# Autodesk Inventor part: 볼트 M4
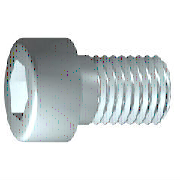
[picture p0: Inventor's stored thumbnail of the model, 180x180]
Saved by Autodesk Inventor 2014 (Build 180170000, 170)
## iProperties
IsCustomPart: 0
Created: 2016-04
Part Number: 볼트 M4
Material: 강철, 연강
Description: 6각머리 태핑 나사
Document SubType Name: Modeling
Standard: KS B 1003
Designer: mdu
Standards Organization: KS
Language: ko-KR
Size Designation: M 4 x 10
Categories: <MemberInstance><Categories><Category DisplayName="조임쇠" InternalName="e4da775c-781d-43d5-af7c-5136215cf5a6" Mnemonic="FSTN"><Category DisplayName="볼트" InternalN
Density: 7.86 g/cm^3
Mass: 2.0371 g
Surface Area: 3.0572 cm^2
Volume: 0.259174 cm^3
Appearance: 금속 1800F 열
Author: mdu
Revision Number: 1
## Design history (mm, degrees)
sketch "스케치1"
  geometry: L1 (-1, 0)-(10, 0); L2 (10, 0)-(10, 2); L3 (10, 2)-(1.75, 2); L4 (1.75, 2)-(1.32, 2); L5 (1.32, 2)-(0, 2); L6 (0, 2)-(0, 3.5); L7 (0, 3.5)-(-4, 3.5); L8 (-4, 3.5)-(-4, 1.732); L9 (-4, 1.732)-(-2, 1.732); L10 (-2, 1.732)-(-1, 0); L11 (-6.8, 0)-(12.8, 0) reference; L12 (0, -0.7)-(0, 4.2) reference; L13 (1.75, 2)-(0, 2)
  constraints: 22 end point, 6 parallel, 2 collinear, 2 perpendicular, 1 horizontal, 1 point on line
  dimensions: "d1" = 8.25 distance from line of L3.end L2 (= GEL); "d2" = 0.42952 distance of L4.end L3.end (computed from GAL); "d3" = 4 distance between parallel lines of L8 L6 (= KOH); "d4" = 2 distance of L8.end L9.end (= INTI); "d5" = 60 deg angle of L10 L1; "d6" = 4 diameter of L3 L1 (= GD); "d7" = 4 diameter of L5 L1 (= BDM); "d8" = 3.4641 diameter of L9 L1 (= 1.1547 x SW); "d9" = 7 diameter of L7 L1 (= KOD); "d26" = 10 distance between parallel lines of L12 L2 (= NLG)
revolve "본체" sketch "스케치1" stored, may be unused: angle "d10" = 90 deg
sketch "스케치2"
  geometry: L1 (0, -4.9)-(0, 4.9) reference; L2 (-4.9, 0)-(4.9, 0) reference; L3 (1.732, 0)-(0.866, -1.5); L4 (0.866, -1.5)-(-0.866, -1.5); L5 (-0.866, -1.5)-(-1.732, 0); L6 (-1.732, 0)-(-0.866, 1.5); L7 (-0.866, 1.5)-(0.866, 1.5); L8 (0.866, 1.5)-(1.732, 0); 2 further points
  constraints: 12 end point, 1 coincident, 1 horizontal alignment, 1 point on line, 12 other
extrude "슬롯" join sketch "스케치2" stored distance "d11" = 10; taper "d12" = 0 deg
workplane "Work Plane1"
fillet "Fillet2" dims "d30" = 0.1 (= R)
body "Solid1"
fillet "모깎기1" dims "d17" = 0.4 (= RR)
feature "스레드" dims "d13" = 8.25 (= GEL), "d14" = 0
chamfer "모따기1" distance "d15" = 0.42941 (= -0.5 x SPD + 0.5 x GD); stored, may be unused: second distance "d16" = 0.42941 (= GUL), angle "d27" = 45 deg
other parameters: "GD" = 4 (= NND) [user parameter; used in 2 equation terms], "NLG" = 10 [user parameter; used in 1 equation term], "GEL" = 8.25 [user parameter; used in 2 equation terms], "KOD" = 7 [user parameter; used in 1 equation term], "KOH" = 4 [user parameter; used in 1 equation term], "INTI" = 2 [user parameter; used in 1 equation term], "GAL" = 0.42941 (= 0.61345 x PTC) [user parameter; used in 1 equation term], "GUL" = 0.42941 (= 0.61345 x PTC) [user parameter; used in 1 equation term], "BDM" = 4 (= NND) [user parameter; used in 1 equation term], "SW" = 3 [user parameter; used in 2 equation terms], "RR" = 0.4 [user parameter; used in 1 equation term], "SPD" = 3.14117 (= NND - 1.2269 x PTC) [user parameter; used in 1 equation term], "d19" = 0, "d28" = 0, "d29" = 0, "R" = 0.1 [user parameter; used in 1 equation term], "PHH" = 0.2 [user parameter], "GD1" = 3.14117 (= THREADDIA - 1.2269 x PTC) [user parameter], "THREADDIA" = 4 [user parameter; used in 1 equation term], "FAWI" = 45 deg [user parameter], "TPU" = 14.28571 (computed from PTC) [user parameter], "PTC" = 0.7 [user parameter; used in 5 equation terms], "NND" = 4 [user parameter; used in 3 equation terms], "TOA" = 30 deg [user parameter], "E0" = 3.465 (= 1.155 x SW) [user parameter]
